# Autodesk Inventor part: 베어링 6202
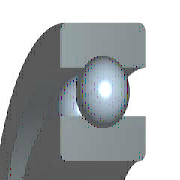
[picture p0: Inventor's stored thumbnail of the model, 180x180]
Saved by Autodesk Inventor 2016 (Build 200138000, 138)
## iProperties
IsCustomPart: 1
Created: 2015-12
Part Number: 베어링 6202
Material: 강철, 연강
Description: 깊은 그루브 볼 베어링
Document SubType Name: Modeling
Standard: KS B 2023
Designer: mdu
Standards Organization: KS
Language: ko-KR
Size Designation: 6202 - 15 x 35 x 11
Categories: <MemberInstance><Categories><Category DisplayName="샤프트 부품" InternalName="7f7aeb1f-a693-4053-b835-cee3144e0d98" Mnemonic="SHFT"><Category DisplayName="베어링" Inter
Density: 7.86 g/cm^3
Mass: 45.8724 g
Surface Area: 51.5584 cm^2
Volume: 5.83618 cm^3
Appearance: 노란색
Author: mdu
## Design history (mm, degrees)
sketch "스케치" dims "d0" = 5.2 (= -0.26 x WD + 0.26 x BD)
  geometry: L1 (2.9, 12.5)-(8.1, 12.5); L2 (5.5, 12.5)-(5.5, 9.9); L3 (5.5, 12.5)-(5.5, 15.1); L4 (3.568, 10.76)-(0, 10.76); L5 (0, 7.5)-(11, 7.5); L6 (3.568, 14.24)-(0, 14.24); L7 (0, 17.5)-(11, 17.5); L8 (11, 7.5)-(11, 10.76); L9 (7.432, 10.76)-(11, 10.76); L10 (7.432, 14.24)-(11, 14.24); L11 (11, 17.5)-(11, 14.24); L12 (-1.4, 0)-(8.4, 0) reference; L13 (0, -0.3)-(0, 5.3) reference
  constraints: 22 end point, 4 point on line, 2 collinear, 2 perpendicular, 2 symmetric about line, 1 midpoint, 1 parallel, 14 other
  dimensions: "d9" = 15 diameter of L5 L12 (= WD); "d11" = 35 diameter of L7 L12 (= BD); "d12" = 11 distance between parallel lines of L8 L13 (= KB); "d13" = 21.52 diameter of L9 L12 (= 0.326 x BD + 0.674 x WD)
revolve "본체" stored, may be unused: angle "d6" = 90 deg
revolve "볼" stored, may be unused: angle "d7" = 90 deg
pattern_circular "IDS_ARRAYBALL[SIMPL:T]" dims angle "d3" = 360 deg
body "Solid1"
fillet "모깎기1" dims "d1" = 0.6 (= KRS)
other parameters: "WD" = 15 [user parameter; used in 5 equation terms], "BD" = 35 [user parameter; used in 5 equation terms], "KB" = 11 [user parameter; used in 1 equation term], "KRS" = 0.6 [user parameter; used in 1 equation term], "d4" = 0, "d5" = 0, "d8" = 0, "d14" = 0, "d15" = 0, "BBA" = 0 [user parameter], "BC0" = 3750000 [user parameter], "BC" = 7800000 [user parameter], "BR" = 17.5 (= 0.5 x BD) [user parameter], "WR" = 7.5 (= 0.5 x WD) [user parameter]
